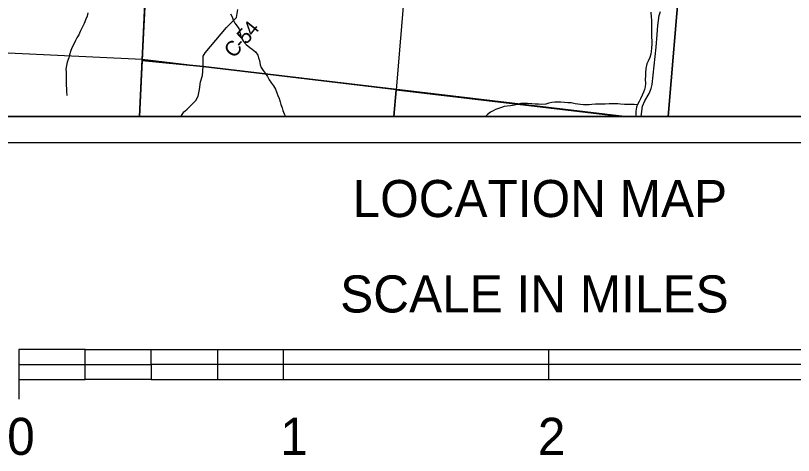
# Model space of a CAD drawing. Extents: x 0 to 34, y 0 to 22.
# Drawn here: x 25.404 to 28.342, y 12.821 to 14.481 of the extents above; entities that cross this region are included whole.
import ezdxf

# ---------------------------------------------------------------- set-up
doc = ezdxf.new("R2010")
doc.units = 0
for name, color, linetype in [('GM_X_County', 7, 'Continuous'), ('GM_X_County_Road', 7, 'Continuous'), ('GM_X_County_Road_Text', 7, 'Continuous'), ('GM_X_Minor_River', 7, 'Continuous'), ('GM_X_Section', 7, 'Continuous'), ('GM_X_Township', 7, 'Continuous'), ('GM_X_Township_Road', 7, 'Continuous'), ('SH_Data', 7, 'Continuous'), ('SH_Text', 7, 'Continuous')]:
    doc.layers.add(name, color=color, linetype=linetype)

msp = doc.modelspace()

# ---------------------------------------------------------------- linework, layer by layer
at = {"layer": 'GM_X_County'}
msp.add_lwpolyline([(24.0167, 20.4902), (24.0167, 14.1), (30.8167, 14.1), (30.8167, 19.9966)], dxfattribs=at)
at = {"layer": 'GM_X_County_Road'}
for points in [[(26.0524, 14.1277), (26.0591, 14.1337), (26.0716, 14.1467), (26.0856, 14.1603), (26.0935, 14.1759), (26.0984, 14.201), (26.1033, 14.231), (26.1101, 14.2549), (26.1128, 14.2885), (26.1123, 14.3081), (26.113, 14.3271), (26.1202, 14.3404), (26.2009, 14.4356), (26.2389, 14.4736), (26.2441, 14.5037)], [(26.0294, 14.1), (26.0296, 14.1006), (26.0402, 14.1166), (26.0432, 14.1193), (26.0524, 14.1277)]]:
    msp.add_lwpolyline(points, dxfattribs=at)
at = {"layer": 'GM_X_Minor_River'}
for points in [[(25.6777, 14.4907), (25.6741, 14.4779), (25.6701, 14.467), (25.6633, 14.45), (25.6559, 14.435), (25.6488, 14.4207), (25.6429, 14.4079), (25.6358, 14.3959), (25.6303, 14.3862), (25.6229, 14.3704), (25.6166, 14.3587), (25.6114, 14.3448), (25.6085, 14.3327), (25.6049, 14.3206), (25.5997, 14.3052), (25.5964, 14.2924), (25.5946, 14.2784), (25.5948, 14.2666), (25.5953, 14.2563), (25.5955, 14.2427), (25.5955, 14.2271), (25.5957, 14.2161), (25.5963, 14.2047), (25.5972, 14.1934), (25.598, 14.1789)], [(26.2162, 14.487), (26.2221, 14.4752), (26.226, 14.4645), (26.2326, 14.4518), (26.2407, 14.441), (26.2473, 14.4311), (26.2506, 14.4211), (26.2537, 14.4093), (26.2569, 14.3983), (26.2646, 14.3829), (26.2757, 14.3714), (26.2884, 14.3594), (26.2981, 14.3542), (26.31, 14.3434), (26.3189, 14.3307), (26.3221, 14.3212), (26.3257, 14.3105), (26.328, 14.2945), (26.332, 14.285), (26.339, 14.2738), (26.3475, 14.2627), (26.3556, 14.2508), (26.3625, 14.2377), (26.3706, 14.2251), (26.378, 14.2154), (26.3865, 14.2028), (26.3915, 14.1886), (26.3951, 14.1783), (26.3998, 14.1672), (26.403, 14.155), (26.4062, 14.1451), (26.4105, 14.1325), (26.4141, 14.1222), (26.4184, 14.1096), (26.4234, 14.1)], [(27.8037, 14.4928), (27.8049, 14.4749), (27.8054, 14.4643), (27.8062, 14.4479), (27.8064, 14.4373), (27.8064, 14.3994), (27.8066, 14.385), (27.8067, 14.3744), (27.8057, 14.3577), (27.8043, 14.3452), (27.803, 14.335), (27.8001, 14.3229), (27.7934, 14.309), (27.7883, 14.2985), (27.7845, 14.2811), (27.7835, 14.2644), (27.7832, 14.2519), (27.7826, 14.2402), (27.7827, 14.2246), (27.7821, 14.2117), (27.78, 14.2019), (27.776, 14.191), (27.7713, 14.1797), (27.7646, 14.1662), (27.7594, 14.1556), (27.7532, 14.1448), (27.7488, 14.1346), (27.7463, 14.1202), (27.7472, 14.1073), (27.7476, 14.1)], [(27.7525, 14.1431), (27.7407, 14.1454), (27.7301, 14.1452), (27.7184, 14.1454), (27.7044, 14.1453), (27.6893, 14.1463), (27.6794, 14.1469), (27.6669, 14.1475), (27.6564, 14.1477), (27.6458, 14.1475), (27.6306, 14.1463), (27.6192, 14.1465), (27.6075, 14.1464), (27.5946, 14.1462), (27.581, 14.145), (27.5711, 14.144), (27.5594, 14.1431), (27.5492, 14.1437), (27.5378, 14.1443), (27.5273, 14.1456), (27.5175, 14.1477), (27.502, 14.1506), (27.4903, 14.1516), (27.4774, 14.1526), (27.4634, 14.1532), (27.4528, 14.1538), (27.4404, 14.1541), (27.4297, 14.1527), (27.418, 14.1499), (27.4069, 14.1467), (27.3902, 14.1451), (27.3793, 14.1457), (27.3672, 14.1463), (27.3543, 14.1473), (27.3381, 14.1484), (27.3248, 14.149), (27.3127, 14.1481), (27.2986, 14.1454), (27.2888, 14.1425), (27.2739, 14.1401), (27.2607, 14.1385), (27.2497, 14.1372), (27.2394, 14.134), (27.228, 14.13), (27.2169, 14.126), (27.2074, 14.1213), (27.1974, 14.1158), (27.187, 14.1076), (27.1791, 14.1)]]:
    msp.add_lwpolyline(points, dxfattribs=at)
at = {"layer": 'GM_X_Section'}
for p, q in [((24.8234, 14.1), (25.8724, 14.1)), ((25.8724, 14.1), (26.8325, 14.1)), ((26.8325, 14.1), (27.694, 14.1)), ((27.694, 14.1), (27.8688, 14.1)), ((27.8688, 14.1), (28.67, 14.1))]:
    msp.add_line(p, q, dxfattribs=at)
for points in [[(25.9296, 15.2643), (25.8818, 14.3145), (24.8423, 14.3642), (24.9048, 15.3211)], [(26.9263, 15.2069), (26.8411, 14.2004), (25.8818, 14.3145), (25.9296, 15.2643)]]:
    msp.add_lwpolyline(points, close=True, dxfattribs=at)
for points in [[(27.8688, 14.1), (27.9567, 15.147), (26.9263, 15.2069), (26.8411, 14.2004), (27.694, 14.1)], [(28.67, 14.1), (28.7351, 15.051), (27.9603, 15.1837), (27.9567, 15.147), (27.8688, 14.1)], [(25.8724, 14.1), (25.8818, 14.3145), (24.8423, 14.3642), (24.8234, 14.1)], [(26.8325, 14.1), (26.8411, 14.2004), (25.8818, 14.3145), (25.8724, 14.1)], [(27.694, 14.1), (26.8411, 14.2004), (26.8325, 14.1)]]:
    msp.add_lwpolyline(points, dxfattribs=at)
at = {"layer": 'GM_X_Township'}
msp.add_line((25.8726, 14.1), (27.704, 14.1), dxfattribs=at)
for points in [[(27.704, 14.1), (30.8167, 14.1), (30.8167, 19.9966)], [(25.8726, 14.1), (25.8823, 14.3113), (25.9155, 15.0123), (25.9233, 15.2144), (25.926, 15.2732), (25.9261, 15.2869), (25.9768, 16.2716), (26.0061, 16.8119)], [(26.0061, 16.8119), (25.9768, 16.2716), (25.9261, 15.2869), (25.926, 15.2732), (25.9233, 15.2144), (25.9155, 15.0123), (25.8823, 14.3113), (26.1128, 14.2885), (27.704, 14.1)], [(24.0167, 16.2296), (24.0167, 14.1), (25.8726, 14.1)], [(27.704, 14.1), (26.1128, 14.2885), (25.8823, 14.3113), (25.8726, 14.1)]]:
    msp.add_lwpolyline(points, dxfattribs=at)
at = {"layer": 'GM_X_Township_Road'}
msp.add_lwpolyline([(27.7671, 14.1), (27.7725, 14.1392), (27.7806, 14.1583), (27.7972, 14.1867), (27.8045, 14.2051), (27.8086, 14.2199), (27.8241, 14.3607), (27.8269, 14.4092), (27.8305, 14.4436), (27.8354, 14.4804), (27.8399, 14.4965)], dxfattribs=at)
at = {"layer": 'SH_Data'}
for p, q in [((25.6667, 13.22), (25.4167, 13.22)), ((25.4167, 13.22), (25.4167, 13.1638)), ((25.6667, 13.22), (25.9167, 13.22)), ((25.6667, 13.1638), (25.6667, 13.22)), ((25.9167, 13.1638), (25.9167, 13.22)), ((25.9167, 13.22), (26.1667, 13.22)), ((26.1667, 13.22), (26.4167, 13.22)), ((26.1667, 13.22), (26.1667, 13.1638)), ((26.4167, 13.1638), (26.4167, 13.22)), ((26.4167, 13.22), (27.4167, 13.22)), ((27.4167, 13.22), (28.4167, 13.22)), ((27.4167, 13.22), (27.4167, 13.1638)), ((25.4167, 13.1638), (25.4167, 13.0325)), ((25.4167, 13.1638), (25.6667, 13.1638)), ((25.6667, 13.1638), (25.9167, 13.1638)), ((25.6667, 13.1075), (25.6667, 13.1638)), ((25.9167, 13.1638), (25.9167, 13.1075)), ((26.1667, 13.1638), (25.9167, 13.1638)), ((26.4167, 13.1638), (26.1667, 13.1638)), ((26.1667, 13.1638), (26.1667, 13.1075)), ((26.4167, 13.1075), (26.4167, 13.1638)), ((27.4167, 13.1638), (26.4167, 13.1638)), ((28.4167, 13.1638), (27.4167, 13.1638)), ((27.4167, 13.1638), (27.4167, 13.1075)), ((25.4167, 13.1075), (25.6667, 13.1075)), ((25.9167, 13.1075), (25.6667, 13.1075)), ((25.9167, 13.1075), (26.1667, 13.1075)), ((26.1667, 13.1075), (26.4167, 13.1075)), ((26.4167, 13.1075), (27.4167, 13.1075)), ((27.4167, 13.1075), (28.4167, 13.1075))]:
    msp.add_line(p, q, dxfattribs=at)
for points in [[(23.9167, 21), (30.9167, 21), (30.9167, 14), (23.9167, 14)], [(24.0167, 20.9), (30.8167, 20.9), (30.8167, 14.1), (24.0167, 14.1)]]:
    msp.add_lwpolyline(points, close=True, dxfattribs=at)

# ---------------------------------------------------------------- texts
at = {"layer": 'GM_X_County_Road_Text'}
for s, rotation, p in [('4', 51.1527, (26.3023, 14.3983)), ('5', 45.9936, (26.2743, 14.3689)), ('C', 49.5168, (26.2291, 14.3167)), ('-', 48.275, (26.2592, 14.3519))]:
    msp.add_text(s, height=0.0568, rotation=rotation, dxfattribs=at).set_placement(p)
at = {"layer": 'SH_Text'}
for s, p in [('LOCATION MAP', (26.677, 13.72)), ('SCALE IN MILES', (26.6302, 13.36)), ('0', (25.3726, 12.8225)), ('1', (26.4037, 12.8225)), ('2', (27.3766, 12.8225))]:
    msp.add_text(s, height=0.14, dxfattribs=at).set_placement(p)

doc.saveas('drawing.dxf')
